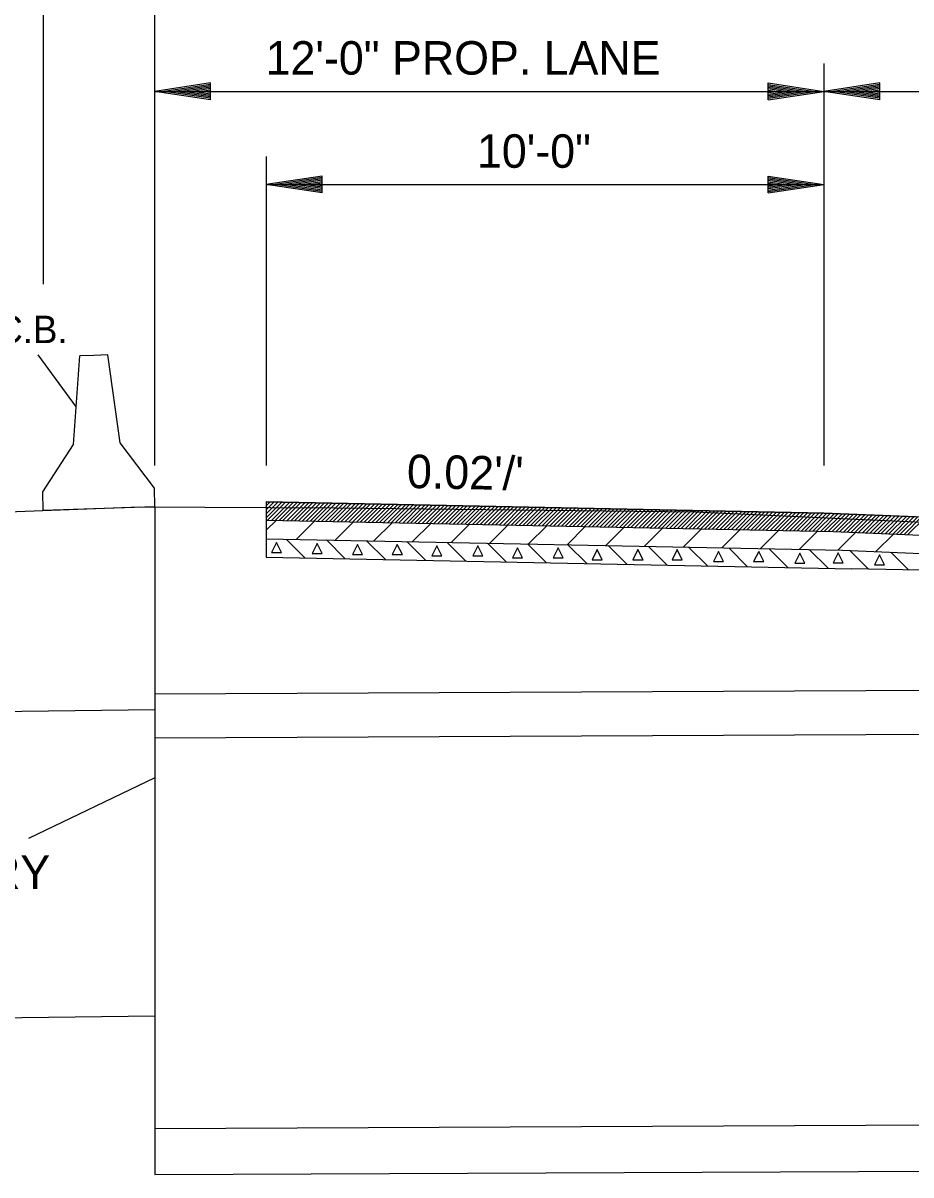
# Model space of a CAD drawing. Extents: x 1398460 to 1408037, y 380768 to 383968.
# Drawn here: x 1399843.1 to 1400002.3, y 383118.5 to 383325.1 of the extents above; entities that cross this region are included whole.
import ezdxf

# ---------------------------------------------------------------- set-up
doc = ezdxf.new("R2010")
doc.units = 0
for name, color, linetype in [('Default', 7, 'Continuous'), ('R_Dimension', 7, 'Continuous'), ('R_Draft', 7, 'Continuous'), ('R_Exist Surface', 7, 'Continuous'), ('R_Water', 7, 'Continuous')]:
    doc.layers.add(name, color=color, linetype=linetype)

msp = doc.modelspace()

# ---------------------------------------------------------------- linework, layer by layer
at = {"layer": 'Default'}
for p, q in [((1399852.11, 383249.52), (1399853.27, 383265.4)), ((1399855.77, 383265.48), (1399853.27, 383265.4)), ((1399858.26, 383265.56), (1399855.77, 383265.48)), ((1399860.45, 383249.79), (1399858.26, 383265.56)), ((1399866.62, 383241.65), (1399860.45, 383249.79)), ((1399846.63, 383241), (1399852.11, 383249.52)), ((1399866.67, 383238.32), (1399866.62, 383241.65)), ((1399846.67, 383237.67), (1399846.63, 383241)), ((1399866.67, 383238.32), (1399846.67, 383237.67))]:
    msp.add_line(p, q, dxfattribs=at)
at = {"layer": 'R_Dimension'}
for p, q in [((1399846.67, 383354.35), (1399846.67, 383278.26)), ((1399866.67, 383245.72), (1399866.67, 383346.05)), ((1399986.67, 383317.81), (1399986.67, 383245.72)), ((1399876.67, 383314.31), (1399866.67, 383312.81)), ((1399876.67, 383314.06), (1399868.34, 383312.81)), ((1399876.67, 383313.81), (1399870.06, 383312.81)), ((1399876.67, 383311.31), (1399876.67, 383314.31)), ((1399976.67, 383314.31), (1399986.67, 383312.81)), ((1399976.67, 383311.31), (1399976.67, 383314.31)), ((1399976.67, 383314.06), (1399985, 383312.81)), ((1399976.67, 383313.81), (1399983.28, 383312.81)), ((1399996.67, 383314.31), (1399986.67, 383312.81)), ((1399996.67, 383314.06), (1399988.34, 383312.81)), ((1399996.67, 383313.81), (1399990.06, 383312.81)), ((1399996.67, 383311.31), (1399996.67, 383314.31)), ((1399876.67, 383311.31), (1399866.67, 383312.81)), ((1399866.67, 383312.81), (1399986.67, 383312.81)), ((1399876.67, 383311.56), (1399868.34, 383312.81)), ((1399876.67, 383311.82), (1399870.06, 383312.81)), ((1399876.67, 383313.56), (1399871.72, 383312.81)), ((1399876.67, 383312.07), (1399871.72, 383312.81)), ((1399876.67, 383313.3), (1399873.42, 383312.81)), ((1399876.67, 383312.33), (1399873.42, 383312.81)), ((1399876.67, 383313.05), (1399875.09, 383312.81)), ((1399876.67, 383312.58), (1399875.09, 383312.81)), ((1399976.67, 383313.56), (1399981.61, 383312.81)), ((1399976.67, 383313.3), (1399979.92, 383312.81)), ((1399976.67, 383313.05), (1399978.25, 383312.81)), ((1399976.67, 383311.31), (1399986.67, 383312.81)), ((1399976.67, 383312.33), (1399979.92, 383312.81)), ((1399976.67, 383311.82), (1399983.28, 383312.81)), ((1399976.67, 383311.56), (1399985, 383312.81)), ((1399976.67, 383312.07), (1399981.61, 383312.81)), ((1399976.67, 383312.58), (1399978.25, 383312.81)), ((1399986.67, 383312.81), (1400046.67, 383312.81)), ((1399996.67, 383311.31), (1399986.67, 383312.81)), ((1399996.67, 383311.56), (1399988.34, 383312.81)), ((1399996.67, 383311.82), (1399990.06, 383312.81)), ((1399996.67, 383313.56), (1399991.72, 383312.81)), ((1399996.67, 383312.07), (1399991.72, 383312.81)), ((1399996.67, 383313.3), (1399993.42, 383312.81)), ((1399996.67, 383312.33), (1399993.42, 383312.81)), ((1399996.67, 383313.05), (1399995.09, 383312.81)), ((1399996.67, 383312.58), (1399995.09, 383312.81)), ((1399886.67, 383301.11), (1399886.67, 383245.72)), ((1399896.67, 383297.61), (1399886.67, 383296.11)), ((1399896.67, 383297.36), (1399888.34, 383296.11)), ((1399896.67, 383294.61), (1399896.67, 383297.61)), ((1399976.67, 383297.61), (1399986.67, 383296.11)), ((1399976.67, 383294.61), (1399976.67, 383297.61)), ((1399976.67, 383297.36), (1399985, 383296.11)), ((1399896.67, 383294.61), (1399886.67, 383296.11)), ((1399886.67, 383296.11), (1399986.67, 383296.11)), ((1399896.67, 383294.86), (1399888.34, 383296.11)), ((1399896.67, 383297.11), (1399890.06, 383296.11)), ((1399896.67, 383295.12), (1399890.06, 383296.11)), ((1399896.67, 383296.86), (1399891.72, 383296.11)), ((1399896.67, 383295.37), (1399891.72, 383296.11)), ((1399896.67, 383296.6), (1399893.42, 383296.11)), ((1399896.67, 383295.63), (1399893.42, 383296.11)), ((1399896.67, 383296.35), (1399895.09, 383296.11)), ((1399896.67, 383295.88), (1399895.09, 383296.11)), ((1399976.67, 383297.11), (1399983.28, 383296.11)), ((1399976.67, 383296.86), (1399981.61, 383296.11)), ((1399976.67, 383296.6), (1399979.92, 383296.11)), ((1399976.67, 383296.35), (1399978.25, 383296.11)), ((1399976.67, 383294.61), (1399986.67, 383296.11)), ((1399976.67, 383295.63), (1399979.92, 383296.11)), ((1399976.67, 383295.12), (1399983.28, 383296.11)), ((1399976.67, 383294.86), (1399985, 383296.11)), ((1399976.67, 383295.37), (1399981.61, 383296.11)), ((1399976.67, 383295.88), (1399978.25, 383296.11)), ((1399845.72, 383265.56), (1399852.6, 383256.2)), ((1399866.67, 383189.72), (1399844.07, 383178.85))]:
    msp.add_line(p, q, dxfattribs=at)
at = {"layer": 'R_Draft'}
for p, q in [((1399886.67, 383239.21), (1399986.67, 383237.21)), ((1399886.67, 383239.21), (1399886.67, 383235.91)), ((1399886.67, 383238.5), (1399887.36, 383239.2)), ((1399886.67, 383237.8), (1399888.05, 383239.18)), ((1399886.67, 383237.09), (1399888.75, 383239.17)), ((1399886.67, 383236.38), (1399889.44, 383239.16)), ((1399886.9, 383235.91), (1399890.13, 383239.14)), ((1399887.59, 383235.89), (1399890.83, 383239.13)), ((1399888.28, 383235.88), (1399891.52, 383239.11)), ((1399888.98, 383235.86), (1399892.21, 383239.1)), ((1399889.67, 383235.85), (1399892.9, 383239.09)), ((1399890.36, 383235.84), (1399893.6, 383239.07)), ((1399891.06, 383235.82), (1399894.29, 383239.06)), ((1399891.75, 383235.81), (1399894.98, 383239.05)), ((1399892.44, 383235.8), (1399895.68, 383239.03)), ((1399893.14, 383235.78), (1399896.37, 383239.02)), ((1399893.83, 383235.77), (1399897.06, 383239)), ((1399894.52, 383235.75), (1399897.76, 383238.99)), ((1399895.21, 383235.74), (1399898.45, 383238.98)), ((1399895.91, 383235.73), (1399899.14, 383238.96)), ((1399896.6, 383235.71), (1399899.84, 383238.95)), ((1399897.29, 383235.7), (1399900.53, 383238.93)), ((1399897.99, 383235.68), (1399901.22, 383238.92)), ((1399898.68, 383235.67), (1399901.92, 383238.91)), ((1399899.37, 383235.66), (1399902.61, 383238.89)), ((1399900.07, 383235.64), (1399903.3, 383238.88)), ((1399900.76, 383235.63), (1399904, 383238.86)), ((1399901.45, 383235.62), (1399904.69, 383238.85)), ((1399902.15, 383235.6), (1399905.38, 383238.84)), ((1399902.84, 383235.59), (1399906.08, 383238.82)), ((1399903.53, 383235.57), (1399906.77, 383238.81)), ((1399904.23, 383235.56), (1399907.46, 383238.8)), ((1399904.92, 383235.55), (1399908.16, 383238.78)), ((1399905.61, 383235.53), (1399908.85, 383238.77)), ((1399906.31, 383235.52), (1399909.54, 383238.75)), ((1399907, 383235.5), (1399910.24, 383238.74)), ((1399907.69, 383235.49), (1399910.93, 383238.73)), ((1399908.39, 383235.48), (1399911.62, 383238.71)), ((1399909.08, 383235.46), (1399912.32, 383238.7)), ((1399909.77, 383235.45), (1399913.01, 383238.68)), ((1399910.47, 383235.43), (1399913.7, 383238.67)), ((1399911.16, 383235.42), (1399914.4, 383238.66)), ((1399911.85, 383235.41), (1399915.09, 383238.64)), ((1399912.55, 383235.39), (1399915.78, 383238.63)), ((1399913.24, 383235.38), (1399916.48, 383238.62)), ((1399913.93, 383235.37), (1399917.17, 383238.6)), ((1399914.63, 383235.35), (1399917.86, 383238.59)), ((1399915.32, 383235.34), (1399918.55, 383238.57)), ((1399916.01, 383235.32), (1399919.25, 383238.56)), ((1399916.71, 383235.31), (1399919.94, 383238.55)), ((1399917.4, 383235.3), (1399920.63, 383238.53)), ((1399918.09, 383235.28), (1399921.33, 383238.52)), ((1399918.79, 383235.27), (1399922.02, 383238.5)), ((1399919.48, 383235.25), (1399922.71, 383238.49)), ((1399920.17, 383235.24), (1399923.41, 383238.48)), ((1399920.86, 383235.23), (1399924.1, 383238.46)), ((1399921.56, 383235.21), (1399924.79, 383238.45)), ((1399922.25, 383235.2), (1399925.49, 383238.44)), ((1399922.94, 383235.19), (1399926.18, 383238.42)), ((1399923.64, 383235.17), (1399926.87, 383238.41)), ((1399924.33, 383235.16), (1399927.57, 383238.39)), ((1399925.02, 383235.14), (1399928.26, 383238.38)), ((1399925.72, 383235.13), (1399928.95, 383238.37)), ((1399926.41, 383235.12), (1399929.65, 383238.35)), ((1399927.1, 383235.1), (1399930.34, 383238.34)), ((1399927.8, 383235.09), (1399931.03, 383238.32)), ((1399928.49, 383235.07), (1399931.73, 383238.31)), ((1399929.18, 383235.06), (1399932.42, 383238.3)), ((1399929.88, 383235.05), (1399933.11, 383238.28)), ((1399930.57, 383235.03), (1399933.81, 383238.27)), ((1399931.26, 383235.02), (1399934.5, 383238.25)), ((1399931.96, 383235), (1399935.19, 383238.24)), ((1399932.65, 383234.99), (1399935.89, 383238.23)), ((1399933.34, 383234.98), (1399936.58, 383238.21)), ((1399934.04, 383234.96), (1399937.27, 383238.2)), ((1399934.73, 383234.95), (1399937.97, 383238.19)), ((1399935.42, 383234.94), (1399938.66, 383238.17)), ((1399936.12, 383234.92), (1399939.35, 383238.16)), ((1399936.81, 383234.91), (1399940.05, 383238.14)), ((1399937.5, 383234.89), (1399940.74, 383238.13)), ((1399938.2, 383234.88), (1399941.43, 383238.12)), ((1399938.89, 383234.87), (1399942.13, 383238.1)), ((1399939.58, 383234.85), (1399942.82, 383238.09)), ((1399940.28, 383234.84), (1399943.51, 383238.07)), ((1399940.97, 383234.82), (1399944.2, 383238.06)), ((1399941.66, 383234.81), (1399944.9, 383238.05)), ((1399942.36, 383234.8), (1399945.59, 383238.03)), ((1399943.05, 383234.78), (1399946.28, 383238.02)), ((1399943.74, 383234.77), (1399946.98, 383238.01)), ((1399944.44, 383234.76), (1399947.67, 383237.99)), ((1399945.13, 383234.74), (1399948.36, 383237.98)), ((1399945.82, 383234.73), (1399949.06, 383237.96)), ((1399946.51, 383234.71), (1399949.75, 383237.95)), ((1399947.21, 383234.7), (1399950.44, 383237.94)), ((1399947.9, 383234.69), (1399951.14, 383237.92)), ((1399948.59, 383234.67), (1399951.83, 383237.91)), ((1399949.29, 383234.66), (1399952.52, 383237.89)), ((1399949.98, 383234.64), (1399953.22, 383237.88)), ((1399950.67, 383234.63), (1399953.91, 383237.87)), ((1399951.37, 383234.62), (1399954.6, 383237.85)), ((1399952.06, 383234.6), (1399955.3, 383237.84)), ((1399952.75, 383234.59), (1399955.99, 383237.82)), ((1399953.45, 383234.58), (1399956.68, 383237.81)), ((1399954.14, 383234.56), (1399957.38, 383237.8)), ((1399954.83, 383234.55), (1399958.07, 383237.78)), ((1399955.53, 383234.53), (1399958.76, 383237.77)), ((1399956.22, 383234.52), (1399959.46, 383237.76)), ((1399956.91, 383234.51), (1399960.15, 383237.74)), ((1399957.61, 383234.49), (1399960.84, 383237.73)), ((1399958.3, 383234.48), (1399961.54, 383237.71)), ((1399958.99, 383234.46), (1399962.23, 383237.7)), ((1399959.69, 383234.45), (1399962.92, 383237.69)), ((1399960.38, 383234.44), (1399963.62, 383237.67)), ((1399961.07, 383234.42), (1399964.31, 383237.66)), ((1399961.77, 383234.41), (1399965, 383237.64)), ((1399962.46, 383234.39), (1399965.7, 383237.63)), ((1399963.15, 383234.38), (1399966.39, 383237.62)), ((1399963.85, 383234.37), (1399967.08, 383237.6)), ((1399964.54, 383234.35), (1399967.78, 383237.59)), ((1399965.23, 383234.34), (1399968.47, 383237.58)), ((1399965.93, 383234.33), (1399969.16, 383237.56)), ((1399966.62, 383234.31), (1399969.85, 383237.55)), ((1399967.31, 383234.3), (1399970.55, 383237.53)), ((1399968.01, 383234.28), (1399971.24, 383237.52)), ((1399968.7, 383234.27), (1399971.93, 383237.51)), ((1399969.39, 383234.26), (1399972.63, 383237.49)), ((1399970.09, 383234.24), (1399973.32, 383237.48)), ((1399970.78, 383234.23), (1399974.01, 383237.46)), ((1399971.47, 383234.21), (1399974.71, 383237.45)), ((1399972.16, 383234.2), (1399975.4, 383237.44)), ((1399972.86, 383234.19), (1399976.09, 383237.42)), ((1399973.55, 383234.17), (1399976.79, 383237.41)), ((1399974.24, 383234.16), (1399977.48, 383237.4)), ((1399974.94, 383234.15), (1399978.17, 383237.38)), ((1399886.67, 383235.91), (1399988.33, 383233.88)), ((1399886.67, 383235.91), (1399886.67, 383229.31)), ((1399886.67, 383234.12), (1399888.42, 383235.88)), ((1399892.12, 383232.5), (1399895.35, 383235.74)), ((1399899.05, 383232.36), (1399902.28, 383235.6)), ((1399905.98, 383232.22), (1399909.22, 383235.46)), ((1399912.91, 383232.09), (1399916.15, 383235.32)), ((1399975.63, 383234.13), (1399978.87, 383237.37)), ((1399976.32, 383234.12), (1399979.56, 383237.35)), ((1399977.02, 383234.1), (1399980.25, 383237.34)), ((1399977.71, 383234.09), (1399980.95, 383237.33)), ((1399978.4, 383234.08), (1399981.64, 383237.31)), ((1399979.1, 383234.06), (1399982.33, 383237.3)), ((1399979.79, 383234.05), (1399983.03, 383237.28)), ((1399980.48, 383234.03), (1399983.72, 383237.27)), ((1399981.18, 383234.02), (1399984.41, 383237.26)), ((1399981.87, 383234.01), (1399985.11, 383237.24)), ((1399982.56, 383233.99), (1399985.8, 383237.23)), ((1399983.26, 383233.98), (1399986.49, 383237.21)), ((1399983.95, 383233.97), (1399987.18, 383237.19)), ((1399984.64, 383233.95), (1399987.86, 383237.16)), ((1399985.34, 383233.94), (1399988.54, 383237.14)), ((1399986.03, 383233.92), (1399989.22, 383237.11)), ((1399986.67, 383237.21), (1400046.67, 383234.81)), ((1399986.72, 383233.91), (1399989.9, 383237.08)), ((1399987.42, 383233.9), (1399990.58, 383237.06)), ((1399988.11, 383233.88), (1399991.26, 383237.03)), ((1399988.79, 383233.86), (1399991.94, 383237)), ((1399989.47, 383233.83), (1399992.62, 383236.97)), ((1399990.15, 383233.8), (1399993.3, 383236.95)), ((1399990.83, 383233.78), (1399993.97, 383236.92)), ((1399991.51, 383233.75), (1399994.65, 383236.89)), ((1399992.19, 383233.72), (1399995.33, 383236.86)), ((1399992.87, 383233.7), (1399996.01, 383236.84)), ((1399993.55, 383233.67), (1399996.69, 383236.81)), ((1399994.23, 383233.64), (1399997.37, 383236.78)), ((1399994.91, 383233.61), (1399998.05, 383236.76)), ((1399995.59, 383233.59), (1399998.73, 383236.73)), ((1399996.27, 383233.56), (1399999.41, 383236.7)), ((1399996.95, 383233.53), (1400000.09, 383236.67)), ((1399997.63, 383233.51), (1400000.77, 383236.65)), ((1399998.31, 383233.48), (1400001.45, 383236.62)), ((1399998.99, 383233.45), (1400002.13, 383236.59)), ((1399999.67, 383233.42), (1400002.81, 383236.57)), ((1400000.35, 383233.4), (1400003.49, 383236.54)), ((1400001.03, 383233.37), (1400004.17, 383236.51)), ((1400001.71, 383233.34), (1400004.85, 383236.48)), ((1399919.85, 383231.95), (1399923.08, 383235.18)), ((1399926.78, 383231.81), (1399930.01, 383235.04)), ((1399933.71, 383231.67), (1399936.95, 383234.91)), ((1399940.64, 383231.53), (1399943.88, 383234.77)), ((1399947.57, 383231.39), (1399950.81, 383234.63)), ((1399954.51, 383231.25), (1399957.74, 383234.49)), ((1399961.44, 383231.12), (1399964.67, 383234.35)), ((1399968.37, 383230.98), (1399971.61, 383234.21)), ((1399975.3, 383230.84), (1399978.54, 383234.07)), ((1399982.24, 383230.7), (1399985.47, 383233.93)), ((1399988.33, 383233.88), (1400028.33, 383232.28)), ((1399989.17, 383230.56), (1399992.33, 383233.72)), ((1399995.98, 383230.3), (1399999.13, 383233.45)), ((1399886.67, 383232.61), (1399990, 383230.54)), ((1399890.24, 383232.54), (1399893.61, 383229.17)), ((1399897.46, 383232.39), (1399900.82, 383229.03)), ((1399904.67, 383232.25), (1399908.04, 383228.88)), ((1399911.89, 383232.11), (1399915.25, 383228.74)), ((1399919.1, 383231.96), (1399922.47, 383228.59)), ((1399926.32, 383231.82), (1399929.69, 383228.45)), ((1399933.53, 383231.67), (1399936.9, 383228.31)), ((1399940.75, 383231.53), (1399944.12, 383228.16)), ((1399947.96, 383231.38), (1399951.33, 383228.02)), ((1399955.18, 383231.24), (1399958.55, 383227.87)), ((1399886.67, 383229.31), (1399991.67, 383227.21)), ((1399962.4, 383231.1), (1399965.76, 383227.73)), ((1399969.61, 383230.95), (1399972.98, 383227.58)), ((1399976.83, 383230.81), (1399980.19, 383227.44)), ((1399984.04, 383230.66), (1399987.41, 383227.3)), ((1399990, 383230.54), (1400030, 383228.94)), ((1399991.28, 383230.49), (1399994.62, 383227.15)), ((1399998.65, 383230.2), (1400001.84, 383227.01)), ((1400105.99, 383224.92), (1399991.67, 383227.21))]:
    msp.add_line(p, q, dxfattribs=at)
msp.add_lwpolyline([(1400046.67, 383234.81), (1399986.67, 383237.21), (1399886.67, 383239.21)], dxfattribs=at)
for points in [[(1399887.62, 383230.16), (1399889.42, 383230.16), (1399888.52, 383231.96)], [(1399894.89, 383229.96), (1399896.69, 383229.96), (1399895.79, 383231.76)], [(1399902.11, 383229.75), (1399903.91, 383229.75), (1399903.01, 383231.55)], [(1399909.27, 383229.75), (1399911.07, 383229.75), (1399910.17, 383231.55)], [(1399916.38, 383229.53), (1399918.18, 383229.53), (1399917.28, 383231.33)], [(1399923.7, 383229.53), (1399925.5, 383229.53), (1399924.6, 383231.33)], [(1399930.82, 383229.16), (1399932.62, 383229.16), (1399931.72, 383230.96)], [(1399938.12, 383229.16), (1399939.92, 383229.16), (1399939.02, 383230.96)], [(1399945.12, 383228.85), (1399946.92, 383228.85), (1399946.02, 383230.65)], [(1399952.42, 383228.85), (1399954.22, 383228.85), (1399953.32, 383230.65)], [(1399959.45, 383228.85), (1399961.25, 383228.85), (1399960.35, 383230.65)], [(1399966.85, 383228.52), (1399968.65, 383228.52), (1399967.75, 383230.32)], [(1399974.06, 383228.52), (1399975.86, 383228.52), (1399974.96, 383230.32)], [(1399981.45, 383228.21), (1399983.25, 383228.21), (1399982.35, 383230.01)], [(1399988.31, 383228.28), (1399990.11, 383228.28), (1399989.21, 383230.08)], [(1399995.71, 383227.94), (1399997.51, 383227.94), (1399996.61, 383229.74)]]:
    msp.add_lwpolyline(points, close=True, dxfattribs=at)
at = {"layer": 'R_Exist Surface'}
msp.add_lwpolyline([(1399228.4, 383169.53), (1399274.79, 383147.11), (1399308.64, 383124.96), (1399413.54, 383125.95), (1399518.92, 383119.19), (1399564.54, 383123.9), (1399570.04, 383124.42), (1399644.13, 383173.31), (1399694.66, 383216.79), (1399706.58, 383230.11), (1399724, 383231.42), (1399760.08, 383234.25), (1399794.58, 383235.67), (1399863.93, 383238.34), (1399899.16, 383238.15), (1399963.63, 383237.42), (1399999.02, 383235.82), (1400017.72, 383234.96), (1400035.29, 383232.19), (1400037.12, 383231.82), (1400040.35, 383227.25), (1400054.83, 383215.12), (1400141.21, 383139.52)], dxfattribs=at)
at = {"layer": 'R_Water'}
for p, q in [((1399866.67, 383238.32), (1399866.67, 383118.64)), ((1399866.67, 383204.81), (1400201.35, 383206.39)), ((1400211.35, 383198.47), (1399866.67, 383196.88)), ((1399866.67, 383126.88), (1400302.47, 383128.89)), ((1400302.47, 383120.55), (1399866.67, 383118.55))]:
    msp.add_line(p, q, dxfattribs=at)
msp.add_lwpolyline([(1399866.67, 383146.99), (1399671.14, 383144.55), (1399671.14, 383199.56), (1399866.67, 383202)], dxfattribs=at)

# ---------------------------------------------------------------- texts
at = {"layer": 'R_Dimension'}
for s, p in [('12\'-0" PROP. LANE', (1399886.56, 383315.81)), ('10\'-0"', (1399924.45, 383299.11)), ('TEMPORARY', (1399797.11, 383169.84))]:
    msp.add_text(s, height=6, dxfattribs=at).set_placement(p)
at = {"layer": 'R_Draft'}
msp.add_text('STAGE 2: P.C.C.B.', height=4.9184, dxfattribs=at).set_placement((1399794.05, 383267.67))
msp.add_text("0.02'/'", height=6, rotation=358.8542, dxfattribs=at).set_placement((1399911.85, 383241.71))

doc.saveas('drawing.dxf')
